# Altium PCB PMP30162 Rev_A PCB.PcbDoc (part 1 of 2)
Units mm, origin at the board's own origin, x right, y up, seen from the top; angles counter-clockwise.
Board outline 76.83 x 62.23 mm, 2 copper layers (Top Layer, Bottom Layer), stack 1.575 mm thick; 72 components, 34 nets, 157 pads, 116 vias.
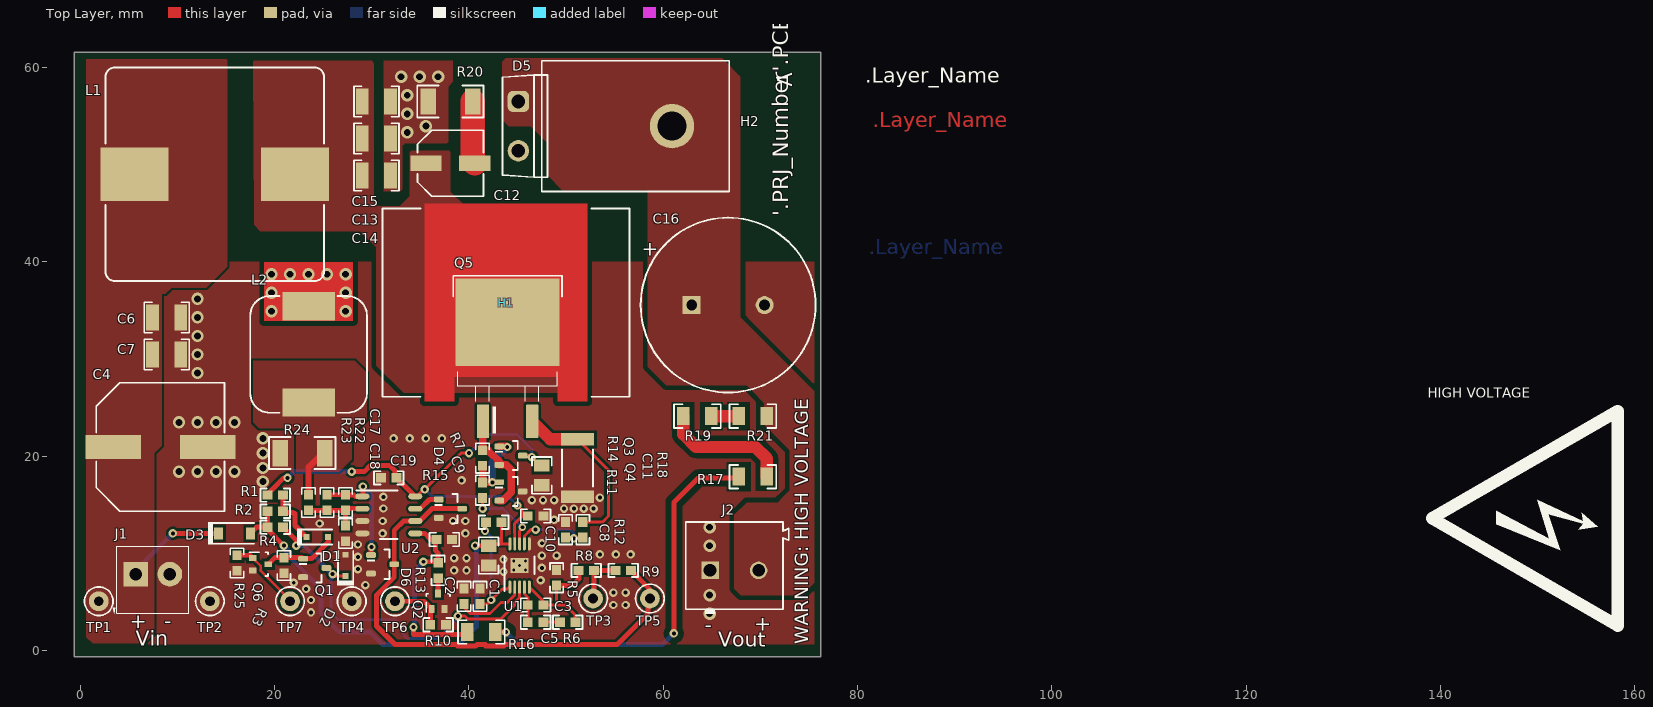
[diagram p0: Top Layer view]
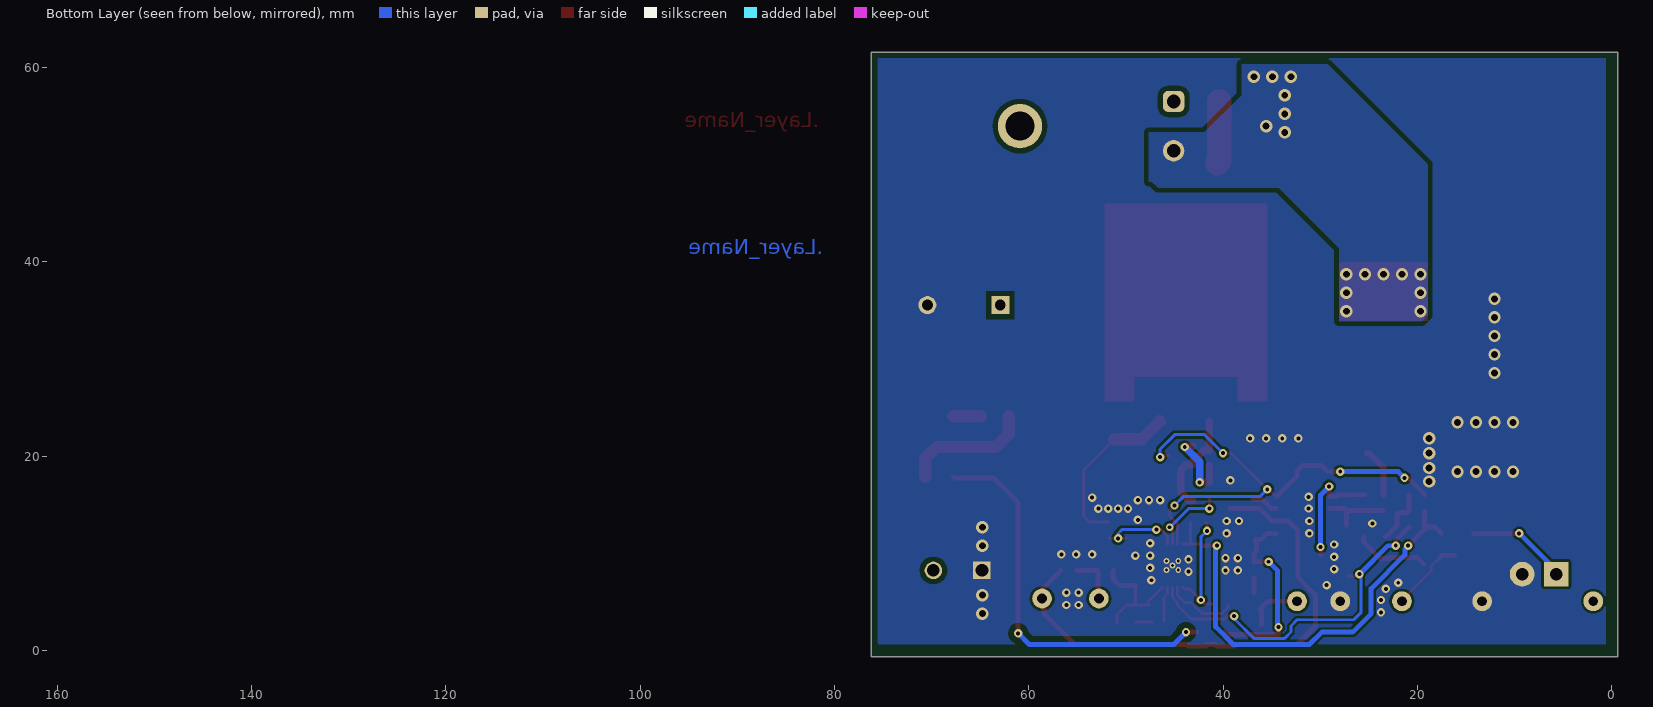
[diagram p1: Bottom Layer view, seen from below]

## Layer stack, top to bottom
Top Solder: solder mask 0.0102, Solder Resist, Dk 3.5
Top Layer: signal copper 0.0356
Dielectric1: core 1.5037, FR-4, Dk 4.8
Bottom Layer: signal copper 0.0356
Bottom Solder: solder mask 0.0102, Solder Resist, Dk 3.5

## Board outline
-0.635,-0.635 -0.635,61.595 76.2,61.595 76.2,-0.635

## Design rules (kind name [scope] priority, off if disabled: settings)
AcuteAngle [All] p1: minimum=4.50000000000000E+0001 checktracksonly=FALSE
AssemblyTestPointUsage [All] p1: valid=2
BoardOutlineClearance BoardOutlineClearance_MountingHoles [OnCopper and InComponentClass('Mounting Holes')] p1: gap=1.016
BoardOutlineClearance BoardOutlineClearance_Poly [OnCopper and IsPoly] p2: gap=0.635
BoardOutlineClearance [OnCopper and Not InComponentClass('Logo') and not InComponentClass('FiducialMark') and not InRegion(1000,500,4000,800) and not InPoly] p3: gap=1.905
Clearance "Schematic Clearance Constraint_31" [InNet('NetR17_1')] p1: gap=0.508
Clearance "Schematic Clearance Constraint_30" [InNet('NetR19_1')] p2: gap=0.508
Clearance "Schematic Clearance Constraint_29" [InNet('NetC16_1')] p3: gap=0.508
Clearance "Schematic Clearance Constraint_28" [InNet('NetC13_1')] p4: gap=0.508
Clearance "Schematic Clearance Constraint_27" [InNet('NetC12_2')] p5: gap=0.508
Clearance "Schematic Clearance Constraint_26" [InNet('NetC12_1')] p6: gap=0.508
Clearance "Schematic Clearance Constraint_25" [InNet('NetR13_2')] p7: gap=0.254
Clearance "Schematic Clearance Constraint_24" [InNet('NetR11_1')] p8: gap=0.254
Clearance "Schematic Clearance Constraint_23" [InNet('NetR8_2')] p9: gap=0.254
Clearance "Schematic Clearance Constraint_22" [InNet('NetQ5_3')] p10: gap=0.254
Clearance "Schematic Clearance Constraint_20" [InNet('NetQ3_2')] p11: gap=0.254
Clearance "Schematic Clearance Constraint_19" [InNet('NetQ3_1')] p12: gap=0.254
Clearance "Schematic Clearance Constraint_18" [InNet('NetQ2_3')] p13: gap=0.254
Clearance "Schematic Clearance Constraint_17" [InNet('NetL2_2')] p14: gap=0.254
Clearance "Schematic Clearance Constraint_16" [InNet('NetD4_1')] p15: gap=0.254
Clearance "Schematic Clearance Constraint_15" [InNet('NetD2_1')] p16: gap=0.254
Clearance "Schematic Clearance Constraint_14" [InNet('NetD1_2')] p17: gap=0.254
Clearance "Schematic Clearance Constraint_13" [InNet('NetD1_1')] p18: gap=0.254
Clearance "Schematic Clearance Constraint_12" [InNet('NetC17_2')] p19: gap=0.254
Clearance "Schematic Clearance Constraint_11" [InNet('NetC17_1')] p20: gap=0.254
Clearance "Schematic Clearance Constraint_10" [InNet('NetC9_1')] p21: gap=0.254
Clearance "Schematic Clearance Constraint_9" [InNet('NetC8_1')] p22: gap=0.254
Clearance "Schematic Clearance Constraint_8" [InNet('NetC5_2')] p23: gap=0.254
Clearance "Schematic Clearance Constraint_7" [InNet('NetC3_2')] p24: gap=0.254
Clearance "Schematic Clearance Constraint_6" [InNet('NetC3_1')] p25: gap=0.254
Clearance "Schematic Clearance Constraint_5" [InNet('NetC2_1')] p26: gap=0.254
Clearance "Schematic Clearance Constraint_4" [InNet('NetC1_1')] p27: gap=0.254
Clearance "Schematic Clearance Constraint_3" [InNet('DISABLE')] p28: gap=0.254
Clearance "Schematic Clearance Constraint_2" [InNet('CS')] p29: gap=0.254
Clearance "Schematic Clearance Constraint_1" [InNet('160V-180V-VCONTROL')] p30: gap=0.254
Clearance "Schematic Clearance Constraint" [InNet('8VBIAS')] p31: gap=0.254
Clearance "Schematic Clearance Constraint_21" [InNet('NetC4_1')] p32: gap=0.254
Clearance Clearance_Keepouts [((IsTrack Or IsArc) And Not InPoly) And IsFree and IsKeepOut vs ((IsTrack Or IsArc) And Not InPoly) And IsFree and IsKeepOut] p33: gap=0
Clearance Clearance_Poly [InPolygon] p34: gap=0.635
Clearance [All] p35: gap=0.2
ComponentClearance ComponentClearance_MountingHoles_FiducialMarks [InComponentClass('Mounting Holes') vs InComponentClass('FiducialMark')] p1: gap=1.27 collisioncheckmode=3 verticalgap=0.254 showdistances=FALSE
ComponentClearance ComponentClearance_Shunt [InComponentClass('Header') vs InComponentClass('Shunt')] p2: gap=0 collisioncheckmode=3 verticalgap=0 showdistances=FALSE
ComponentClearance ComponentClearance_Logo [InComponentClass('Logo')] p3: gap=1.27 collisioncheckmode=3 verticalgap=0.254 showdistances=FALSE
ComponentClearance ComponentClearance_ScrewToNut [(HasFootprint('NY PMS 440 0025 PH')) vs (HasFootprint('Keystone_1902C'))] p4: gap=0.127 collisioncheckmode=3 verticalgap=0.254 showdistances=FALSE
ComponentClearance ComponentClearance_MountingHoles [InComponentClass('Mounting Holes')] p5: gap=6.35 collisioncheckmode=3 verticalgap=2540 showdistances=FALSE
ComponentClearance ComponentClearance_SmallPassives [HasFootprint('0201*') or HasFootprint('0402*') or HasFootprint('0508') or HasFootprint('0603*') or HasFootprint('0612') or HasFootprint('0805*') or HasFootprint('0815*') or HasFootprint('0830*') or HasFootprint('1206*') or HasFootprint('1210*') or HasFootprint('1808*') or HasFootprint('1812*') or HasFootprint('1825*') or HasFootprint('2010*') or HasFootprint('2220*') or HasFootprint('2225*') or HasFootprint('2512*') or HasFootprint('2728*') or HasFootprint('3518*') vs HasFootprint('0201*') or HasFootprint('0402*') or HasFootprint('0508') or HasFootprint('0603*') or HasFootprint('0612') or HasFootprint('0805*') or HasFootprint('0815*') or HasFootprint('0830*') or HasFootprint('1206*') or HasFootprint('1210*') or HasFootprint('1808*') or HasFootprint('1812*') or HasFootprint('1825*') or HasFootprint('2010*') or HasFootprint('2220*') or HasFootprint('2225*') or HasFootprint('2512*') or HasFootprint('2728*') or HasFootprint('3518*')] p6: gap=0.38 collisioncheckmode=3 verticalgap=0.254 showdistances=FALSE
ComponentClearance ComponentClearance_THtoSMT [IsThruComponent vs IsSMTComponent] p7: gap=1.016 collisioncheckmode=3 verticalgap=0.762 showdistances=FALSE
ComponentClearance ComponentClearance_THtoTH [IsThruComponent vs IsThruComponent] p8: gap=0.762 collisioncheckmode=3 verticalgap=0.762 showdistances=FALSE
ComponentClearance [All] p9: gap=0.762 collisioncheckmode=3 verticalgap=0.254 showdistances=FALSE
DiffPairsRouting [All] p1: maxlimit=2.54 minlimit=0.254 mostfreqgap=0.254 toplayer_minwidth=0.381 toplayer_maxwidth=0.381 toplayer_prefwidth=0.381 bottomlayer_minwidth=0.381 bottomlayer_maxwidth=0.381 bottomlayer_prefwidth=0.381 maxuncoupledlength=25.4
FabricationTestPointUsage TestPointUsage [All] p1: valid=2 allowmultiple=FALSE
FabricationTestpoint Testpoint [All] p1: side=3 testpointundercomponent=TRUE minsize=1.016 maxsize=2.54 preferedsize=1.524 minholesize=0 maxholesize=1.016 preferedholesize=0.813 testpointgrid=0.025 allowsidetop=TRUE allowsidebottom=TRUE usegrid=TRUE gridtolerance=0
FanoutControl Fanout_LCC [IsLCC] p1: bgadir=Out bgaviamode=Centered fanoutstyle=Auto fanoutdirection=Alternating viagrid=0.025 // Fanout_LCC (Default Rule)
FanoutControl Fanout_BGA [IsBGA] p2: bgadir=Out bgaviamode=Centered fanoutstyle=Auto fanoutdirection=Alternating viagrid=0.025 // Fanout_BGA (Default Rule)
FanoutControl Fanout_Default [All] p4: bgadir=Out bgaviamode=Centered fanoutstyle=Auto fanoutdirection=Alternating viagrid=0.025 // Fanout_Default (Default Rule)
FanoutControl Fanout_Small [(CompPinCount < 5)] p5: bgadir=Out bgaviamode=Centered fanoutstyle=Auto fanoutdirection=OutThenIn viagrid=0.025 // Fanout_Small (Default Rule)
HoleSize [All] p1: absolutevalues=TRUE maxlimit=6.375 minlimit=0.3 maxpercent=80.000 minpercent=20.000
MinimumAnnularRing MinimumAnnularRing_ThermalPadVias [IsVia and InAnyComponent] p1: minimumring=0.15
MinimumAnnularRing [All] p2: minimumring=0.203
MinimumSolderMaskSliver MinimumSolderMaskSliver_Logo [InComponentClass('Logo') vs InComponentClass('Logo')] p1: minsoldermaskwidth=0.018
MinimumSolderMaskSliver [All] p2: minsoldermaskwidth=0.1
PlaneConnect [All] p1: planeconnectstyle=Relief reliefexpansion=0.254 reliefentries=4 reliefconductorwidth=0.254 reliefairgap=0.254
PolygonConnect PolygonConnect_9 [All vs IsNamedPolygon('Top Layer-No Net 2')] p1: connectstyle=Direct reliefconductorwidth=0.254 reliefentries=4 polygonreliefangle="90 Angle" airgapwidth=0.254
PolygonConnect PolygonConnect_8 [All vs IsNamedPolygon('Bottom Layer-No Net 3')] p2: connectstyle=Direct reliefconductorwidth=0.254 reliefentries=4 polygonreliefangle="90 Angle" airgapwidth=0.254
PolygonConnect PolygonConnect_7 [All vs IsNamedPolygon('Bottom Layer-No Net 2')] p3: connectstyle=Direct reliefconductorwidth=0.254 reliefentries=4 polygonreliefangle="90 Angle" airgapwidth=0.254
PolygonConnect PolygonConnect_6 [All vs IsNamedPolygon('Bottom Layer-No Net 1')] p4: connectstyle=Direct reliefconductorwidth=0.254 reliefentries=4 polygonreliefangle="90 Angle" airgapwidth=0.254
PolygonConnect PolygonConnect_5 [All vs IsNamedPolygon('Bottom Layer-No Net')] p5: connectstyle=Direct reliefconductorwidth=0.254 reliefentries=4 polygonreliefangle="90 Angle" airgapwidth=0.254
PolygonConnect PolygonConnect_4 [All vs IsNamedPolygon('Bottom Layer-No Net')] p6: connectstyle=Direct reliefconductorwidth=0.254 reliefentries=4 polygonreliefangle="90 Angle" airgapwidth=0.254
PolygonConnect PolygonConnect_3 [All vs IsNamedPolygon('TOP_LAYER_NETC13_1_P004')] p7: connectstyle=Direct reliefconductorwidth=0.254 reliefentries=4 polygonreliefangle="90 Angle" airgapwidth=0.254
PolygonConnect PolygonConnect_2 [All vs IsNamedPolygon('Top Layer-No Net 1')] p8: connectstyle=Direct reliefconductorwidth=0.254 reliefentries=4 polygonreliefangle="90 Angle" airgapwidth=0.254
PolygonConnect PolygonConnect_1 [All vs IsNamedPolygon('Top Layer-No Net')] p9: connectstyle=Direct reliefconductorwidth=0.254 reliefentries=4 polygonreliefangle="90 Angle" airgapwidth=0.254
PolygonConnect [All] p10: connectstyle=Relief reliefconductorwidth=0.254 reliefentries=4 polygonreliefangle="90 Angle" airgapwidth=0.254
RoutingVias ThermalPadVias [IsVia and InAnyComponent] p1: holewidth=0.3 width=0.7 viastyle="Through Hole" minholewidth=0.3 minwidth=0.6 maxholewidth=0.5 maxwidth=1
RoutingVias [All] p2: holewidth=0.4 width=0.864 viastyle="Through Hole" minholewidth=0.3 minwidth=0.6 maxholewidth=1.016 maxwidth=1.651
SilkToBoardRegionClearance [Not ((IsComment or IsDesignator) And (Hide <> 'False')) and not InRegion(1000,500,4000,800)] p1:
SilkToSilkClearance SilkToSilkClearance_Pb-FreeLogo [(HasFootprint('Pb-Free_Overlay_Medium') OR HasFootprint('Pb-Free_Overlay_Small')) vs (HasFootprint('Pb-Free_Overlay_Medium') OR HasFootprint('Pb-Free_Overlay_Small'))] p1: silktosilkclearance=0
SilkToSilkClearance [All] p2: silktosilkclearance=0.102
SilkToSolderMaskClearance SilkToComponentPadClearance [IsPad and InAnycomponent] p1: minsilkscreentomaskgap=0.127 clearancetoexposedcopper=TRUE
SilkToSolderMaskClearance "Silk to Solder Mask Opening" [All] p2: minsilkscreentomaskgap=0.102 clearancetoexposedcopper=FALSE
SolderMaskExpansion [All] p1: expansion=0.05
Width [All] p1: maxlimit=2.54 minlimit=0.152 preferedwidth=0.254 checkconnectedcopper=TRUE
15 further rules are at their usual default settings.

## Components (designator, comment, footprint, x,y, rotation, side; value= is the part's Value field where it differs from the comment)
C1 "GRM188R71H331KA01D" 0603 41.148,5.588 r90 top
C2 "GRM188R71E224KA88D" 0603 39.497,5.588 r90 top
C3 "C0603C121J5GACTU" 0603 46.863,4.699 r0 top
C4 "EMVY800ATR101MKE0S" CAPSMT_62_KE0 8.255,20.955 r0 top
C5 "GRM188R71E563KA01D" 0603 46.863,2.921 r0 top
C6 "C1210C225K1RACTU" 1210_210 8.89,34.29 r0 top
C7 "C1210C225K1RACTU" 1210_210 8.89,30.48 r0 top
C8 "06033C101KAT2A" 0603 49.944,12.446 r90 top
C9 "GRM21BR71H105KA12L" 0805_HV 42.037,9.779 r270 top
C10 "GCM188R71H104KA57D" 0603 46.863,13.843 r0 top
C11 "GRM21BR71H105KA12L" 0805_HV 47.498,18.034 r270 top
C12 "EEE-FK1V680XP" SM_RADIAL_D8 38.1,50.165 r0 top
C13 "C1210C225K1RACTU" 1210_210 30.48,52.705 r180 top
C14 "C1210C225K1RACTU" 1210_210 30.48,48.895 r180 top
C15 "C1210C225K1RACTU" 1210_210 30.48,56.515 r180 top
C16 "EEUED2E101S" CAPPR7.5-18X25 66.675,35.56 r0 top
C17 "GRM188R71H102KA01D" 0603 27.305,15.24 r90 top
C18 "GRM188R71H103KA01D" 0603 27.305,12.065 r90 top
C19 "GCM188R71H104KA57D" 0603 31.75,17.78 r0 top
D1 "MMSZ5246BS-7-F" SOD-323 24.384,11.684 r0 top
D2 "MMSZ5235BS-7-F" sod-323 27.305,8.763 r90 top
D3 "MMSZ5250B-7-F" SOD-123 15.875,12.065 r0 top
D4 "BAS16-7-F" SOT-23 38.1,14.605 r0 top
D5 "LQA06T300" TO-220AC 45.085,53.975 r270 top
D6 "BAS16-7-F" SOT-23 31.115,8.89 r0 top
H1 "7109DG" Aavid_7109DG 43.815,35.814 r0 top
H2 "274-2AB" HEATSINK_274-2AB 57.15,53.975 r270 top
"HIGH VOLTAGE" "DANGER HIGH VOLTAGE" IEC_HighVoltage_Large 149.301,13.614 r90 top
J1 "ED555/2DS" TERM_BLK_ED555-2DS 8.89,6.604 r180 top
J2 "691 101 710 002" Wurth_691101710002 67.945,8.255 r180 top
L1 "74435588200" WE-HCI_2212 13.843,49.022 r0 top
L2 "7447709471" WE-PD_1210 23.495,30.48 r270 top
Q1 "MMBT2222ALT1G" SOT-23 24.13,8.509 r0 top
Q2 "BSS138W-7-F" SOT-323 36.83,5.08 r90 top
Q3 "MMBT2222ALT1G" SOT-23 44.323,20.066 r0 top
Q4 "MMBT2907ALT1G" SOT-23 44.323,16.383 r0 top
Q5 "IPB407N30N" DDPAK 43.972,29.848 r90 top
Q6 "BSS138W-7-F" SOT-323 18.542,8.89 r0 top
R1 "RC0603FR-07200KL" 0603 20.066,16.002 r180 top
R2 "RC0603FR-0739K2L" 0603 20.066,14.351 r180 top
R3 "CRCW0603100KFKEA" 0603 20.955,8.763 r90 top
R4 "RC0603FR-0747K5L" 0603 20.066,12.7 r180 top
R5 "RC0603FR-0715KL" 0603 49.022,7.493 r270 top
R6 "RC0603FR-07137KL" 0603 50.165,2.921 r180 top
R7 "RC0603FR-07523KL" 0603 42.545,13.208 r0 top
R8 "RC0603FR-0738K3L" 0603 52.07,8.255 r0 top
R9 "CRCW060349R9FKEA" 0603 55.88,8.255 r0 top
R10 "CRCW060310K0FKEA" 0603 36.83,2.667 r0 top
R11 "RC0603FR-072R21L" 0603 41.402,16.51 r90 top
R12 "CRCW06031K00FKEA" 0603 51.722,12.446 r90 top
R13 "RC0603FR-07130KL" 0603 36.83,8.255 r90 top
R14 "RC0603FR-07100RL" 0603 41.402,19.812 r90 top
R15 "RC0603FR-0715K4L" 0603 37.465,11.43 r180 top
R16 "ERJ-8ENF2493V" 1206 41.275,1.905 r180 top
R17 "ERJ-8ENF2493V" 1206 69.215,17.899 r180 top
R18 "ERJ-M1WSF20MU" 2512 51.181,18.796 r90 top
R19 "ERJ-8ENF2493V" 1206 63.5,24.13 r180 top
R20 "CRCW201010R0FKEF" 2010 38.1,56.515 r180 top
R21 "ERJ-8ENF2493V" 1206 69.215,24.13 r180 top
R22 "RC0603FR-0722K6L" 0603 25.4,15.24 r270 top
R23 "CRCW06031K00FKEA" 0603 23.495,15.24 r270 top
R24 "CSR2010FTR150" 2010 22.86,20.32 r180 top
R25 "CRCW060310K0FKEA" 0603 16.129,9.017 r270 top
TP1 "5000" Keystone5000 1.905,5.08 r0 top
TP2 "5001" Keystone5001 13.335,5.08 r0 top
TP3 "5003" Keystone5003 52.781,5.359 r0 top
TP4 "5001" Keystone5001 27.94,5.08 r0 top
TP5 "5000" Keystone5000 58.623,5.359 r0 top
TP6 "5000" Keystone5000 32.385,5.08 r0 top
TP7 "5000" Keystone5000 21.59,5.08 r0 top
U1 "TPS40210DGQR" DGQ0010D_N 45.212,8.763 r90 top
U2 "TLC272CD" D0008A_N 31.75,13.97 r0 top

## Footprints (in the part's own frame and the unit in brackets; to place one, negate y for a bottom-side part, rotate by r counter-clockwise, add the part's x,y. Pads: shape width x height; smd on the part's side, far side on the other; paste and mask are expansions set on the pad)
0603 [mm] "0603 from SM-752 data"
  rect 1x0.95 smd: 1(-0.8,0) 2(0.8,0)
  silkscreen extent -1.52,-0.69 1.52,0.69, body extent -0.87,-0.47 0.87,0.47, height 1
0805_HV [mil] "0805 with 30mil clearance between pads"
  rect 50x63 smd: 1(-40,0) 2(40,0)
  silkscreen extent -74,-40 74,40, body extent -43,-29 43,29, height 57
1206 [mm] "1206 from SM-752 data"
  rect 1.3x1.85 smd: 1(-1.45,0) 2(1.45,0)
  silkscreen extent -2.4,-1.21 2.4,1.21, body extent -1.7,-0.9 1.7,0.9, height 1.35
1210_210 [mm] "1210"
  rect 1.3x2.7 smd: 1(-1.45,0) 2(1.45,0)
  silkscreen extent -2.32,-1.57 2.32,1.57, body extent -1.7,-1.35 1.7,1.35, height 2.1
2010 [mm] "Chip Capacitor, Body 5.08x2.54mm, IPC Medium Density"
  rect 1.6x2.7 smd: 1(-2.3,0) 2(2.3,0)
  silkscreen extent -3.42,-1.65 3.42,1.65, body extent -2.73,-1.45 2.73,1.45, height 1.66
2512 [mm] "Chip Resistor, Body 6.3x3.2mm, IPC Medium Density"
  rect 1.3x3.4 smd: 1(-2.95,0) 2(2.95,0)
  silkscreen extent -1.9,-1.6 1.9,1.6, body extent -3.22,-1.67 3.22,1.67, height 0.71
Aavid_7109DG [mm] "Surface mount heat sink for D2PAK"
  rect 5x5 smd: 1(0,0)
  Top Layer region: -8.38,-10.16 -8.38,10.16 8.38,10.16 8.38,-10.16 5.335,-10.16 5.335,-7.62 -5.335,-7.62 -5.335,-10.16
  silkscreen extent -12.7,-9.69 12.7,9.69, body extent -12.7,-9.69 12.7,9.69, height 12.03
CAPPR7.5-18X25 [mm] "Capacitor, Electrolytic, Radial; Body 18 x 25 mm (Dia.xH typ); Pin Spacing 7.5 mm (typ)"
  rect 1.85x1.85 hole 1.1: 1(-3.75,0)
  round 1.85 hole 1.1: 2(3.75,0)
  silkscreen extent -9,-9 9,9, body extent -9,-9.01 9,9.01, height 27
CAPSMT_62_KE0 [mm] "12.5 x 13.5mm:  Chemi-Con KE0"
  rect 5.7x2.5 smd: 1(-4.85,0) 2(4.85,0)
  silkscreen extent -6.6,-6.6 6.6,6.6, body extent -6.6,-6.6 6.6,6.6, height 14
D0008A_N [mm] "SOIC, 8-Leads, Body 4.9x3.9mm, Pitch 1.27mm, IPC Medium Density"
  oval 1.45x0.6 smd: 1(-2.725,1.905) 2(-2.725,0.635) 3(-2.725,-0.635) 4(-2.725,-1.905) 5(2.725,-1.905) 6(2.725,-0.635) 7(2.725,0.635) 8(2.725,1.905)
  silkscreen extent -3.3,-2.5 0.9,2.5, body extent -3,-2.45 3,2.45, height 1.63
DDPAK [mil] "D2-PAK, 3-Pads, Body 9.7x10.4mm (max), TO-263AB, using Vishay Silionix recommended pad sizes"
  rrect8% 135x49.49 smd: 1(-246.06,100) 3(-246.06,-100)
  rrect1% 355x420 smd paste-181.1: 4(155.51,0)
  silkscreen extent -295,-220 344,220, body extent -295,-202 324,202, height 180
DGQ0010D_N [mm] "TSSOP, 10-Leads, Body 3x3mm, Pitch 0.5mm, Thermal Pad 1.88x1.57mm, IPC Medium Density"
  rrect100% 1.35x0.3 smd: 1(-2.225,1) 2(-2.225,0.5) 3(-2.225,0) 4(-2.225,-0.5) 5(-2.225,-1) 6(2.225,-1) 7(2.225,-0.5) 8(2.225,0) 9(2.225,0.5) 10(2.225,1)
  rrect6% 1.57x1.88 smd: 11(0,0)
  silkscreen extent -2.65,-1.55 0.9,1.55, body extent -2.46,-1.5 2.46,1.5, height 1.1
HEATSINK_274-2AB [mil] "HEATSINK LOW HEIGHT BLK TO-220, 4-40 screw"
  round 1 on Mech3: 0(0,0)
  round 180 hole 118: 1(0,147.64)
  silkscreen extent -265,-380 265,380, body extent -260,-376 260,376, height 501
IEC_HighVoltage_Large [mm]
  silkscreen extent -11.05,-8.94 11.05,10.2
Keystone5000 [mil] "For Keystone 500x miniature loop terminals"
  round 80 hole 40: 1(0,0)
  silkscreen extent -58,-58 58,58, body extent -49,-49 49,49, height 182
Keystone5001 [mil] "For Keystone 500x miniature loop terminals"
  round 80 hole 40: 1(0,0)
  silkscreen extent -58,-58 58,58, body extent -49,-49 49,49, height 182
Keystone5003 [mil] "For Keystone 500x miniature loop terminals"
  round 80 hole 40: 1(0,0)
  silkscreen extent -58,-58 58,58, body extent -49,-49 49,49, height 182
SM_RADIAL_D8 [mm] "6.3 x 7.7mm:  Panasonic D8"
  rect 3.2x1.6 smd: 1(-2.5,0) 2(2.5,0)
  silkscreen extent -3.4,-3.4 3.4,3.4, body extent -3.4,-3.4 3.4,3.4, height 8.01
SOD-123 [mm] "On Semi recommended land pattern"
  rect 0.915x1.22 smd: 1(-1.637,0) 2(1.637,0)
  silkscreen extent -2.74,-1.17 2.03,1.17, body extent -1.93,-0.9 1.93,0.9, height 1.35
SOD-323 [mm] "NXP recommended land pattern"
  rect 0.6x0.6 smd paste-0.05: 1(-1.1,0) 2(1.1,0)
  silkscreen extent -2.06,-0.86 1.53,0.86, body extent -1.3,-0.67 1.3,0.68, height 1.1
sod-323 [mm] "NXP recommended land pattern"
  rect 0.6x0.6 smd paste-0.05: 1(-1.1,0) 2(1.1,0)
  silkscreen extent -2.06,-0.86 1.53,0.86, body extent -1.3,-0.67 1.3,0.68, height 1.1
SOT-23 [mm] "SOT23, 3-Leads, Body 2.9x1.3mm, Pitch 0.95mm, Lead Span 2.5mm, IPC Medium Density"
  rrect50% 1x0.6 smd: 1(-1.2,0.95) 2(-1.2,-0.95) 3(1.2,0)
  silkscreen extent -1.63,-1.5 0.7,1.5, body extent -1.16,-1.45 1.21,1.45, height 1
SOT-323 [mm] "Zetex recommended land pattern.  March 2007"
  rect 0.8x0.6 smd: 1(-0.8,0.65) 2(-0.8,-0.65) 3(0.8,0)
  silkscreen extent -1.14,-1.22 0.77,1.22, body extent -1.13,-1.13 1.12,1.12, height 1.13
TERM_BLK_ED555-2DS [mil]
  rrect4% 100x100 hole 50: 1(125,-50)
  round 100 hole 50: 2(-13,-50)
  silkscreen extent -90,-163 218,111, body extent -82,-156 194,100, height 323
TO-220AC [mm]
  rrect50% 2.2x2.2 hole 1.4: 1(-2.54,0)
  round 2.2 hole 1.4: 3(2.54,0)
  silkscreen extent -5.25,-1.64 5.26,3.01, body extent -5.25,-1.64 5.26,3.01, height 19.09
WE-HCI_2212 [mm] "SMD, 2-Leads, Body 22.5x22mm"
  rect 7x5.5 smd: 1(-8.25,0) 2(8.25,0)
  silkscreen extent -11.25,-11 11.25,11, body extent -11.25,-11 11.25,11, height 12.01
WE-PD_1210 [mm] "Wurth Elektronik recommended land pattern"
  rect 2.9x5.4 smd: 1(-4.95,0) 2(4.95,0)
  silkscreen extent -6,-6 6,6, body extent -6,-6 6,6, height 10.01
Wurth_691101710002 [mm] "Terminal Block, 5 mm, 2x1, TH"
  rect 1.8x1.8 hole 1.3: 1(3.135,0)
  round 1.8 hole 1.3: 2(-1.865,0)
  silkscreen extent -4.96,-5 5.64,4.5, body extent -4.97,-5 6.23,4, height 12.5

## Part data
C1: "CAP, CERM, 330pF, 50V, +/-10%, X7R, 0603"
C2: "CAP, CERM, 0.22uF, 25V, +/-10%, X7R, 0603"
C3: "CAP, CERM, 120 pF, 50 V, +/- 5%, C0G/NP0, 0603"
C4: "CAP, AL, 100 µF, 80 V, +/- 20%, 0.33 ohm, SMD"
C5: "CAP, CERM, 0.056 µF, 25 V, +/- 10%, X7R, 0603"
C6 C7 C13 C14 C15: "CAP, CERM, 2.2 µF, 100 V, +/- 10%, X7R, 1210"
C8: "CAP, CERM, 100pF, 25V, +/-10%, X7R, 0603"
C9 C11: "CAP, CERM, 1uF, 50V, +/-10%, X7R, 0805"
C10 C19: "CAP, CERM, 0.1uF, 50V, +/-10%, X7R, 0603"
C12: "CAP, AL, 68 µF, 35 V, +/- 20%, 0.34 ohm, AEC-Q200 Grade 2, SMD"
C16: "CAP, AL, 100 µF, 250 V, +/- 20%, 0.243706 ohm, TH"
C17: "CAP, CERM, 1000pF, 50V, +/-10%, X7R, 0603"
C18: "CAP, CERM, 0.01uF, 50V, +/-10%, X7R, 0603"
D1: "Diode, Zener, 16 V, 200 mW, SOD-323"
D2: "Diode, Zener, 6.8V, 200mW, SOD-323"
D3: "Diode, Zener, 20 V, 500 mW, SOD-123"
D4 D6: "Diode, Ultrafast, 75V, 0.3A, SOT-23"
D5: "Diode, Schottky, 300 V, 6 A, TH"
H1: "Surface mount heat sink for D2PAK"
H2: "Heat Sink, TO-220, TH"
"HIGH VOLTAGE": library part IEC_HighVoltage, "IEC 61010-1 High Voltage Warning"
J1: "Terminal Block, 6A, 3.5mm Pitch, 2-Pos, TH"
J2: "Terminal Block, 5 mm, 2x1, Tin, TH"
L1: library part 74435580680, "Inductor, Wirewound, Metal Composite, 82 µH, 8.5 A, 0.03 ohm, SMD"
L2: "Inductor, Shielded Drum Core, Ferrite, 470 µH, 1.4 A, 0.56 ohm, SMD"
Q1 Q3: library part "MMBT2222ALT1G, ON Semiconductor", "Transistor, NPN, 40 V, 0.6 A, SOT-23"
Q2 Q6: "MOSFET, N-CH, 50 V, 0.2 A, SOT-323"
Q4: library part "MMBT2907ALT1G, ON Semiconductor", "Transistor, PNP, 60 V, 0.6 A, SOT-23"
Q5: library part IPB60R190C6, "MOSFET, N-CH, 300 V, 44 A, DDPAK"
R1: "RES, 200 k, 1%, 0.1 W, 0603"
R2: "RES, 39.2 k, 1%, 0.1 W, 0603"
R3: "RES, 100k ohm, 1%, 0.1W, 0603"
R4: "RES, 47.5 k, 1%, 0.1 W, 0603"
R5: "RES, 15.0 k, 1%, 0.1 W, 0603"
R6: "RES, 137 k, 1%, 0.1 W, 0603"
R7: "RES, 523 k, 1%, 0.1 W, 0603"
R8: "RES, 38.3 k, 1%, 0.1 W, 0603"
R9: "RES, 49.9 ohm, 1%, 0.1W, 0603"
R10 R25: "RES, 10.0k ohm, 1%, 0.1W, 0603"
R11: "RES, 2.21, 1%, 0.1 W, 0603"
R12: "RES, 1.00k ohm, 1%, 0.1W, 0603"
R13: "RES, 130 k, 1%, 0.1 W, 0603"
R14: "RES, 100, 1%, 0.1 W, 0603"
R15: "RES, 15.4 k, 1%, 0.1 W, 0603"
R16 R17 R19 R21: "RES, 249 k, 1%, 0.25 W, 1206"
R18: "RES, 0.02, 1%, 1 W, 2512"
R20: "RES, 10.0, 1%, 0.75 W, AEC-Q200 Grade 0, 2010"
R22: "RES, 22.6 k, 1%, 0.1 W, 0603"
R23: "RES, 1.00 k, 1%, 0.1 W, 0603"
R24: "RES, 0.15, 1%, 1 W, 2010"
TP1 TP5 TP6 TP7: "Test Point, Miniature, Red, TH"
TP2 TP4: "Test Point, Miniature, Black, TH"
TP3: "Test Point, Miniature, Orange, TH"
U1: "4.5-V TO 52-V INPUT CURRENT MODE BOOST CONTROLLER, DGQ0010D"
U2: "IC, Precision Dual Operational Amplifiers"

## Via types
v1: diameter 0.864, hole 0.406, Top Layer to Bottom Layer, 72 vias
v2: diameter 1.27, hole 0.711, Top Layer to Bottom Layer, 37 vias
v3: diameter 0.6, hole 0.3, Top Layer to Bottom Layer, 5 vias
v4: diameter 0.8, hole 0.4, Top Layer to Bottom Layer, tented top, 1 vias
v5: diameter 0.864, hole 0.406, Top Layer to Bottom Layer, tented top, 1 vias

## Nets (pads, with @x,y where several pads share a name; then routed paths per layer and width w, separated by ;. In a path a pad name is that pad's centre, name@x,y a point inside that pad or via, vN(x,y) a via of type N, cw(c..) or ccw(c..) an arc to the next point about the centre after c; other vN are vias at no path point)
8VBIAS: C10.1 C11.1 C19.2 Q3.3 R1.2 U1.9 U2.8 | length 50.2
  Top Layer w0.305: U2.8@34.475,15.875 34.605,15.875 35.45,16.72 v1(35.45,16.6) 39.17,20.32 v1(40.005,20.32) ; U1.9@44.712,10.988 44.704,13.081 45.458,13.835 45.458,14.473 v1(44.998,14.933) ; Q3.3@45.523,20.066 46.482,20.066 v1(46.482,19.914)
  Top Layer w0.508: R1.2@19.266,16.002 19.266,16.091 19.858,16.683 19.858,16.687 20.951,17.78 v1(21.331,17.78) ; v1(27.94,18.415) 29.21,18.415 29.845,19.05 31.84,19.05 32.385,18.505 32.385,17.945 C19.2@32.55,17.78 34.455,15.875 U2.8@34.475,15.875
  Bottom Layer w0.305: v1(35.45,16.6) 36.175,15.875 44.056,15.875 v1(44.998,14.933) ; v1(40.005,20.32) 41.91,22.225 44.97,22.225 46.482,20.713 v1(46.482,19.914)
  Bottom Layer w0.508: v1(21.331,17.78) 21.966,18.415 v1(27.94,18.415)
160V-180V-VCONTROL: Q2.1 R10.1 TP6.1 | length 5.8
  Top Layer w0.508: TP6.1@32.385,5.08 35.38,5.08 Q2.1@36.18,4.28 36.03,4.13 R10.1@36.03,2.667
CS: D4.3 D6.3 R9.2 TP5.1 U2.6 | length 54.3
  Top Layer w0.508: D4.3@39.3,14.605 36.195,14.605 34.925,13.335 U2.6@34.475,13.335 33.274,13.335 32.315,12.376 D6.3@32.315,8.89 32.315,7.55 30.48,5.715 30.48,2.54 32.385,0.635 38.802,0.635 38.802,0.472 40.685,0.472 40.848,0.635 41.702,0.635 41.702,0.472 43.585,0.472 43.748,0.635 55.245,0.635 58.42,3.81 58.42,5.156 TP5.1@58.623,5.359 58.623,6.312 R9.2@56.68,8.255
DISABLE: Q6.1 R25.1 TP7.1 | length 7.8
  Top Layer w0.254: Q6.1@17.742,9.54 18.551,8.731 18.551,8.246
  Top Layer w0.305: 18.551,8.246 TP7.1@21.59,5.207
  Top Layer w0.381: TP7.1@21.59,5.08 TP7.1@21.59,5.207
  Top Layer w0.508: R25.1@16.129,9.817 17.465,9.817 Q6.1@17.742,9.54
GND: C1.2 C2.2 C4.2 C6.2 C7.2 C8.2 C9.2 C10.2 C11.2 C16.2 C18.1 C19.1 D2.2 D4.2 D6.2 J1.2 J2.1 Q1.2 Q2.2 Q4.3 Q6.2 R3.1 R5.1 R10.2 R15.1 R18.1 R24.2 R25.2 TP2.1 TP4.1 U1.6 U1.11 U2.3 U2.4
  other v1: 23.749,3.937 54.864,4.699 56.134,4.699 23.749,5.207 54.864,5.969 56.134,5.969 23.241,6.35 29.337,6.731 21.971,6.985 47.371,7.239 43.561,8.128 38.481,8.255 39.751,8.255 28.575,8.382 47.498,8.509 43.561,9.398 38.481,9.525 39.751,9.525 28.575,9.652 47.498,9.779 49.022,9.779 53.467,9.906 55.118,9.906 56.642,9.906 28.575,10.922 47.498,11.049 31.115,12.065 39.624,12.065 24.638,13.081 31.115,13.335 38.354,13.335 39.624,13.335 48.768,13.462 49.784,14.605 50.8,14.605 51.816,14.605 52.832,14.605 31.195,14.629 46.482,15.494 47.625,15.494 48.768,15.494 53.467,15.748 31.195,15.823 39.243,17.526 32.258,21.844 33.909,21.844 35.56,21.844 37.211,21.844
  other v2: 64.77,3.81 64.77,5.715 64.77,10.795 64.77,12.7 18.796,17.399 10.16,18.415 12.065,18.415 13.97,18.415 15.875,18.415 18.796,18.796 18.796,20.32 18.796,21.844 10.16,23.495 12.065,23.495 13.97,23.495 15.875,23.495 12.065,28.575 12.065,30.48 12.065,32.385 12.065,34.29 12.065,36.195
  other v3: 44.612,8.313 45.812,8.313 45.212,8.763 44.612,9.213 45.812,9.213
NetC1_1: C1.1 R7.1 U1.1 | length 12
  Top Layer w0.305: C1.1@41.148,4.788 41.872,4.788 v1(42.291,5.207) 43.434,6.35 43.965,6.35 U1.1@44.153,6.538 ; v1(41.656,12.319) 41.656,13.119 R7.1@41.745,13.208
  Bottom Layer w0.305: v1(41.656,12.319) 42.291,11.684 v1(42.291,5.207)
NetC2_1: C2.1 U1.2 | length 7.4
  Top Layer w0.305: C2.1@39.497,4.788 39.497,4.445 40.132,3.81 42.164,3.81 43.307,4.953 43.942,4.953 44.712,5.723 U1.2@44.712,6.538
NetC3_1: C3.1 C5.1 U1.4 | length 3.8
  Top Layer w0.305: U1.4@45.712,6.538 45.712,5.813 46.101,5.424 46.101,4.737 C3.1@46.063,4.699 C5.1@46.063,2.921
NetC3_2: C3.2 R5.2 R6.1 R8.1 U1.5 | length 12.5
  Top Layer w0.305: U1.5@46.212,6.538 47.663,5.087 C3.2@47.663,4.699 ; C3.2@47.575,4.699 C3.2@47.663,4.699 ; R5.2@49.022,6.693 49.022,4.699 ; R6.1@50.927,2.832 50.927,3.683 49.911,4.699 49.022,4.699 ; C3.2@47.663,4.699 49.022,4.699
  Top Layer w0.508: R5.2@49.022,6.693 50.635,6.693 51.308,7.366 51.308,8.217 R8.1@51.27,8.255
NetC4_1: C4.1 C6.1 C7.1 D3.1 J1.1 L1.1 TP1.1 | length 10.5
  Top Layer w0.508: v1(9.525,12.065) D3.1@14.238,12.065
  Bottom Layer w0.508: J1.1@5.715,7.874 5.715,8.255 v1(9.525,12.065)
NetC5_2: C5.2 R6.2 | length 1.7
  Top Layer w0.305: C5.2@47.282,2.921 R6.2@48.984,2.921
NetC8_1: C8.1 R12.1 U1.7 | length 8.7
  Top Layer w0.305: U1.7@45.712,10.988 45.712,11.803 46.355,12.446 v5(46.863,12.446) ; C8.1@49.944,11.646 50.033,11.557 v1(50.8,11.557) 51.633,11.557 R12.1@51.722,11.646
  Bottom Layer w0.305: v5(46.863,12.446) 50.419,12.446 50.8,12.065 v1(50.8,11.557)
